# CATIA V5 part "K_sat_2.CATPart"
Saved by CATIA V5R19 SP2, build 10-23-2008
Part number: sat 2
Source: Unknown
Publications: "Plan.15"
Material "Aucun"
Bounding box of the stored display mesh (mm): x -63.515 to 63.515, y -63.573 to 63.573, z -18.921 to 41.193
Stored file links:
  G:\Khaled_CFAO_2011\ST2M\ST2M_GR1\mponsin\Khaled\CAD_ThinkMOTION\K_sat_2.CATPart
  C:\Program Files\Dassault Systemes\B20\win_b64\startup\materials\French\Catalog.CATMaterial
  C:\Users\Socar\Documents\thinkmotion\Final\Diff2.CATProduct
  G:\Khaled_CFAO_2011\ST2M\ST2M_GR1\mponsin\Khaled\CAD_ThinkMOTION\K_mponsin.CATProduct
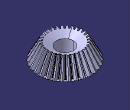
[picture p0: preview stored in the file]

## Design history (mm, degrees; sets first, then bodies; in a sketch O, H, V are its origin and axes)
Parameters
  Z1 = 30 {= External.Zs}
  delta = 26.5651 deg {= atan(External.Zs /External.Zp )}
  a = 20 deg
  m = 4 mm {= External.Module}
  ld = 44.7214 mm {= m *Z1 /(3*2*sin(delta ))}
  dZ = 0 mm
  p = 12.5664 mm {= m * PI}
  rp = 60 mm {= m * Z1 / 2}
  rc = 67.082 mm {= rp / cos( delta )}
  rb = 63.0365 mm {= rc * cos( a )}
  lc = 150 mm {= rc / sin( delta )}
  ha = 4 mm {= m}
  hf = 5 mm {= 1.25 * m}
  rr = 1.4608 mm {= Set2.Offset * 0.7763}
  tc = -0.7576 deg
  ratio = 0.666667 {= 1 - ld / lc / cos( delta )}
External parameters (linked from other documents)
  External.Zp = 60
  External.Zs = 30
  External.Module = 4 mm
Intersect1 "coin de fond": ToIntersect1 Project1, ToIntersect2 Circle4
Point1: type OnCurve, Support Line7, Length 5 {= hf}
Set1 "cones primitifs"
  Line1 "Axe Z": stored without definition
  Point2 "sommet arriere": (0, 0, -30 {= dZ - rp * tan( delta )})
  Point3 "sommet avant": type OnCurve, Support Line1, RefPoint Point2, Length 150 {= lc}
  Line2: type PtPt, FirstPoint Point2, SecondPoint Point3
  Line3: type Angle, RefPoint Point3, Curve Line2, Support zx-plane, Start 0, End 134.1641 {= lc * cos( delta )}, Angle -26.5651 {= -delta}
  Line4: type PtPt, FirstPoint Point2, SecondPoint vertex of Line3, Start 0
  Plane1 "plan_primitif": type OffsetPt, RefPlane xy-plane, RefPoint vertex of Line3
  Intersect2: ToIntersect1 Plane1, ToIntersect2 Line2
  Circle1 "arc primitif": type CtrPt, Start 0, End 30, Center Intersect2, Support Plane1, RefPoint vertex of Line3
  Circle2 "cercle primitif": type CtrRad, Start 0, End 90, Center Intersect2, Support Plane1, Radius 60 {= rp}, FirstDirection (1, 0, 0)
Set2 "profil dent"
  Point4 "point 0": type OnPlane, Support Plane2, RefPoint Point2, H 63.0365, V 0, Direction (1, 0, 0)
  Point5 "point 1": type OnPlane, Support Plane2, RefPoint Point2, H 66.0709, V 0.6451, Direction (1, 0, 0)
  Point6 "point 2": type OnPlane, Support Plane2, RefPoint Point2, H 74.278, V 5.0092, Direction (1, 0, 0)
  Point7 "point 3": type OnPlane, Support Plane2, RefPoint Point2, H 85.116, V 16.077, Direction (1, 0, 0)
  Curve1: Elements (Point4; Point5; Point6; Point7)
  Extrapol1: ToExtrapol Point4, Support Curve1, Length 8 {= 2 * m}
  Plane2: type Normal, Curve Line3, RefPoint Point2
  Symmetry1: Reference vertex of Line3, ToTransfor Point2
  Line5: type PtPt, FirstPoint Point2, SecondPoint Symmetry1
  Point8: type OnCurve, Support Line5, Ratio 0.25
  Line6: type PtPt, FirstPoint Point8, SecondPoint vertex of Line5
  Revol1: Element1 Line6, Line Line1, Angle1 0
  Project1: ToProject Extrapol1, Support Revol1, Direction Line3
  Intersect3: ToIntersect1 Circle1, ToIntersect2 Project1
  Plane3 "plan contact": type 1Line1Pt, RefPoint Intersect3, Line Line1
  Circle3 "cercle primitif": type CtrPt, Start 3 {= 90deg / Z1}, End -3 {= -90deg / Z1}, Center Intersect2, Support Plane1, RefPoint Intersect3
  Plane4 "plan median": type 1Line1Pt, RefPoint vertex of Circle3, Line Line1
  Line7 "droite debut": type PtPt, FirstPoint vertex of Circle3, SecondPoint Point2
  Plane5 "plan_fond": type OffsetPt, RefPlane xy-plane, RefPoint Point1
  Intersect4: ToIntersect1 Plane5, ToIntersect2 Line2
  Circle4 "cercle de fond": type CtrPt, Start 0, End 30, Center Intersect4, Support Plane5, RefPoint Point1
  Point9: type OnCurve, Support Line7, Length -4 {= -ha}
  Plane6 "plan_tete": type OffsetPt, RefPlane xy-plane, RefPoint Point9
  Intersect5: ToIntersect1 Plane6, ToIntersect2 Line2
  Circle5 "cercle de tete": type CtrPt, Start 0, End 30, Center Intersect5, Support Plane6, RefPoint Point9
  Split1 "segment flanc": ToCut Project1, Cutting Plane5
  Split2 "segment fond": ToCut Circle4, Cutting Project1
  Corner1: Element1 Split1, Element2 Split2, Support Revol1, Radius 1.4301 {= Set2.Offset * 0.76}
  Symmetry2: Reference Plane4, ToTransfor Corner1
  Trim1: Element1 Corner1, Element2 Circle5
  Trim2: Element1 Trim1, Element2 Symmetry2
Set3 "surface dent"
  Point10 "fin denture": type OnCurve, Support Line3, Length 44.7214 {= ld}
  Scaling1: Reference Point3, Ratio 0.666667 {= ratio}, ToTransfor Trim2
  Line8: type PtPt, FirstPoint vertex of Scaling1, SecondPoint Point1
  Line9: type PtPt, FirstPoint vertex of Scaling1, SecondPoint vertex of Trim2
  Loft1: Sections (Trim2; Scaling1), Guides (Line8; Line9)
  CircPattern1: of Loft1, instances 30 {= Z1}, angular step 12 {= 360.0*1 deg/CircPattern1.AngularNumber}, axis from Line2
Set4 "flanc dent"
  CircPattern2: of Trim2, instances 30 {= Z1}, angular step 12 {= 360.0*1 deg/CircPattern2.AngularNumber}, axis from Line2
  Join1: Elements (CircPattern2; Trim2)
  Split3: ToCut Revol1, Cutting Join1
  Scaling2: Reference Point3, Ratio 0.666667 {= ratio}, ToTransfor Split3
  Fill1: Boundary edge of Scaling2
  Join2: Elements (Split3; CircPattern1; Scaling2; Fill1; Loft1)
  Plane7: type 1Curve, Element1 edge [face of Shaft1 from Sketch1.L2 | face of Shaft2]
Body1 (main body)
  Sketch1 on zx-plane, origin (0, 0, 0), H (-1, 0, 0), V (0, 0, 1)
    point P1 (-30, -15)
    line L1 (0, 0) -> (0, -18.9213)
    line L2 (0, -18.9213) -> (-30, -18.9213)
    line L3 (-30, -18.9213) -> (-30, -15)
    reference projected point E1 (-30, -15) from Point8
    line L4 (-30, -15) -> (-60, 0)
    point P5 (-60, 0)
    line L5 (0, 0) -> (-60, 0)
    reference projected point E2 (-60, 0) from vertex of Line4
    horizontal: L2 H, L5 H
    vertical: L1 V, L3 V
    coincidence: P1 E1, L1 V, P5 E2
  Shaft1: profile Sketch1, axis Line1, angle 360
  CloseSurface1: CloseElement Join2
  Sketch2 on xy-plane, origin (0, 0, 0), H (1, 0, 0), V (0, 1, 0)
    circle A1 centre (0, 0) radius 20
    radius A1 = 20
  Pocket1: profile Sketch2, direction (0, 0, 1), through (limit type 6), opposite side through (limit type 6)
  Body2
    Sketch3 on zx-plane, origin (0, 0, 0), H (-1, 0, 0), V (0, 0, 1)
      line L1 (0, -30) -> (333.9525, -10)
      point P1 (0, -30)
      point P2 (333.9525, -10)
      line L2 (333.9525, -10) -> (30, -10)
      point P3 (333.9525, -10)
      line L3 (30, -10) -> (30, -20)
      line L4 (30, -20) -> (0, -20)
      point P6 (0, -20)
      line L5 (0, -20) -> (0, -30)
      reference projected point E1 (0, -30) from Point2
      length L3 = 10
      length L4 = 30
      distance L2 H = 10
      length L2 = 303.9525
      coincidence: P1 V, P3 L1, P6 V, P2 P3, P1 E1
      horizontal: L2 H, L4 H
      vertical: L3 V, L5 V
    Shaft2: profile Sketch3, axis Sketch3.L5, angle 360
  Remove1: tool Body2
  Sketch4 on Plane7, origin (0, 0, -18.9213), H (1, 0, 0), V (0, 1, 0)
